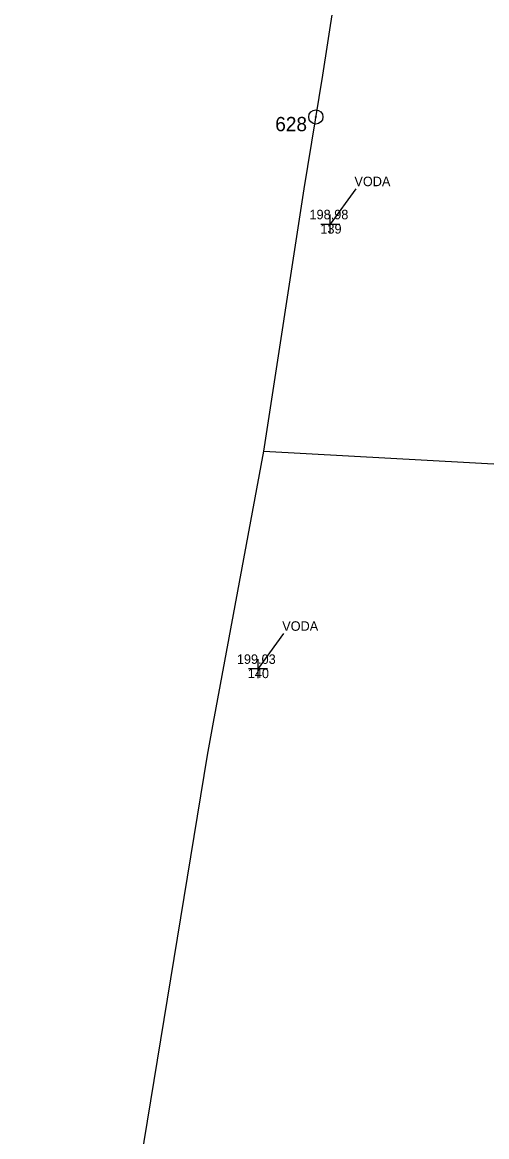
# Model space of a CAD drawing. Extents: x -706631 to -706106, y -1036183 to -1035074.
# Drawn here: x -706279.7 to -706255.3, y -1035795.8 to -1035737.2 of the extents above; entities that cross this region are included whole.
import ezdxf

# ---------------------------------------------------------------- set-up
doc = ezdxf.new("R2010")
doc.units = 0
for name, color, linetype in [('Hranice parcel', 7, 'Continuous'), ('křížky', 7, 'Continuous'), ('Stávající terén', 7, 'Continuous'), ('výšky', 7, 'Continuous'), ('Značky bodu BP', 7, 'Continuous'), ('čísla bodu', 7, 'Continuous')]:
    doc.layers.add(name, color=color, linetype=linetype)

msp = doc.modelspace()

# ---------------------------------------------------------------- linework, layer by layer
at = {"layer": 'Hranice parcel'}
for p, q in [((-706264.29, -1035742.31), (-706263.92, -1035739.95)), ((-706267.01, -1035759.72), (-706236.17, -1035761.41)), ((-706279.73, -1035835.13), (-706269.99, -1035775.7))]:
    msp.add_line(p, q, dxfattribs=at)
for points in [[(-706263.92, -1035739.95), (-706262.46, -1035730.53), (-706259.78, -1035712.37), (-706256.93, -1035694.84)], [(-706267.01, -1035759.72), (-706264.9, -1035745.93), (-706264.29, -1035742.31)], [(-706269.99, -1035775.7), (-706269.67, -1035773.97), (-706267.01, -1035759.72)]]:
    msp.add_lwpolyline(points, dxfattribs=at)
at = {"layer": 'křížky'}
for p, q in [((-706263.52, -1035748.28), (-706263.52, -1035747.28)), ((-706264.02, -1035747.78), (-706263.02, -1035747.78)), ((-706263.52, -1035747.78), (-706263.52, -1035747.78)), ((-706267.32, -1035771.65), (-706267.32, -1035770.65)), ((-706267.82, -1035771.15), (-706266.82, -1035771.15)), ((-706267.32, -1035771.15), (-706267.32, -1035771.15))]:
    msp.add_line(p, q, dxfattribs=at)
at = {"layer": 'Stávající terén'}
for p, q in [((-706262.182, -1035745.927), (-706263.52, -1035747.78)), ((-706265.982, -1035769.297), (-706267.32, -1035771.15))]:
    msp.add_line(p, q, dxfattribs=at)
at = {"layer": 'Značky bodu BP'}
for radius in [0.375, 0.015]:
    msp.add_circle((-706264.28, -1035742.15), radius, dxfattribs=at)
at = {"layer": 'čísla bodu'}
for p, q in [((-706263.52, -1035748.28), (-706263.52, -1035747.28)), ((-706264.02, -1035747.78), (-706263.02, -1035747.78)), ((-706263.52, -1035747.78), (-706263.52, -1035747.78)), ((-706267.32, -1035771.65), (-706267.32, -1035770.65)), ((-706267.82, -1035771.15), (-706266.82, -1035771.15)), ((-706267.32, -1035771.15), (-706267.32, -1035771.15))]:
    msp.add_line(p, q, dxfattribs=at)

# ---------------------------------------------------------------- texts
at = {"layer": 'Stávající terén'}
for p in [(-706262.25, -1035745.79), (-706266.05, -1035769.16)]:
    msp.add_text('VODA', height=0.5, dxfattribs=at).set_placement(p)
at = {"layer": 'výšky'}
for s, p in [('198.98', (-706264.614, -1035747.53)), ('199.03', (-706268.436, -1035770.9))]:
    msp.add_text(s, height=0.5, dxfattribs=at).set_placement(p)
at = {"layer": 'Značky bodu BP'}
msp.add_text('628', height=0.75, dxfattribs=at).set_placement((-706266.417, -1035742.9))
at = {"layer": 'čísla bodu'}
for s, p in [('139', (-706264.042, -1035748.28)), ('140', (-706267.861, -1035771.65))]:
    msp.add_text(s, height=0.5, dxfattribs=at).set_placement(p)

doc.saveas('drawing.dxf')
